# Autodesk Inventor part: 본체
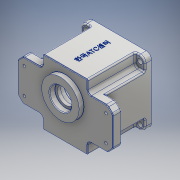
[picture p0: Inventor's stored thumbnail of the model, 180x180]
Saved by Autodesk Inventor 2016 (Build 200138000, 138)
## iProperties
Created: 2017-01
Part Number: 본체
Material: 알루미늄 6061
Document SubType Name: Modeling
Designer: Owner
Density: 2.7 g/cm^3
Appearance: 알루미늄 - 평지
Mass: 908.782 g
Surface Area: 776.692 cm^2
Volume: 336.586 cm^3
Author: Owner
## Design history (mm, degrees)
sketch "스케치1"
  geometry: L1 (70, 30)-(33, 30); L2 (33, 30)-(33, 48); L3 (33, 48)-(-33, 48); L4 (-33, 48)-(-33, 30); L5 (-33, 30)-(-70, 30); L6 (-70, 30)-(-70, -30); L7 (-70, -30)-(-33, -30); L8 (-33, -30)-(-33, -48); L9 (33, -48)-(33, -30); L10 (70, -30)-(70, 30); L11 (70, -30)-(33, -30); L12 (33, -48)-(-33, -48); 1 further point
  constraints: 24 end point, 8 point on line, 5 perpendicular, 3 horizontal, 1 parallel
  dimensions: "d0" = 140 distance between parallel lines of L6 L10; "d2" = 96 distance between parallel lines of L12 L3; "d3" = 70 horizontal distance of L5.end point (0, 0); "d4" = 48 vertical distance of point (0, 0) L3.end; "d5" = 60 distance between parallel lines of L7 L5; "d6" = 30 vertical distance of point (0, 0) L5.end; "d7" = 33 horizontal distance of point (0, 0) L4.end; "d8" = 33 horizontal distance of point (0, 0) L1.end
extrude "돌출1" new body sketch "스케치1" distance "d9" = 13; taper "d10" = 0 deg
sketch "스케치3"
  geometry: L1 (33, -48)-(-33, -48); L2 (-33, -30)-(-33, -48) reference; L3 (-33, -48)-(-33, -30); L4 (-33, -30)-(-47, -30); L5 (-70, -30)-(-33, -30) reference; L6 (-33, 30)-(-70, 30) reference; L7 (-47, 30)-(-33, 30); L8 (-33, 48)-(-33, 30) reference; L9 (-33, 30)-(-33, 48); L10 (33, 48)-(-33, 48) reference; L11 (-33, 48)-(33, 48); L12 (33, 30)-(33, 48) reference; L13 (33, 48)-(33, 30); L14 (33, 30)-(47, 30); L15 (70, 30)-(33, 30) reference; L16 (33, -30)-(70, -30) reference; L17 (47, -30)-(33, -30); L18 (47, -30)-(47, 30); L19 (-47, -30)-(-47, 30); L20 (33, -48)-(33, -30) reference; L21 (33, -48)-(33, -30); 1 further point
  constraints: 24 end point, 6 collinear, 4 point on line, 2 perpendicular, 1 horizontal, 1 vertical
  dimensions: "d12" = 94 distance between parallel lines of L18 L19; "d13" = 47 distance from line of L19 point (0, 0)
extrude "돌출2" join sketch "스케치3" distance "d14" = 57; taper "d15" = 0 deg
sketch "스케치4"
  geometry: L1 (-47, 48)-(47, 48); L2 (47, 48)-(47, -48); L3 (47, -48)-(-47, -48); L4 (-47, -48)-(-47, 48); L5 (-47, 48)-(47, -48); L6 (47, 48)-(-47, -48); L7 (-33, -48)-(33, -48) reference; 2 further points
  constraints: 12 end point, 4 midpoint, 2 parallel, 1 horizontal, 1 perpendicular
  dimensions: "d16" = 94 distance between parallel lines of L4 L2
extrude "돌출3" join sketch "스케치4" distance "d17" = 10; taper "d18" = 0 deg
sketch "스케치5"
  geometry: L1 (0, 0)-(66, 0) reference; L2 (-14, 80)-(80, 80) reference; 3 further points
  constraints: 1 midpoint, 1 vertical alignment, 1 other
  dimensions: "d19" = 40 distance from line of L2 point (33, 40)
feature "엠보싱1" sketch "스케치5" dims "d20" = 0.5, "d21" = 0
sketch "스케치6"
  geometry: L1 (9, 0)-(80, 0); L2 (80, 0)-(80, 43); L3 (80, -48)-(80, 48) reference; L4 (80, 43)-(71, 43); L5 (71, 43)-(71, 40); L6 (71, 40)-(9, 40); L7 (9, 40)-(9, 0); 1 further point
  constraints: 12 end point, 4 perpendicular, 2 horizontal, 1 midpoint, 1 point on line
  dimensions: "d23" = 86 diameter of L4 L1; "d24" = 80 diameter of L6 L1; "d25" = 9 distance of L2.end L4.end; "d26" = 71 distance between parallel lines of L2 L7
revolve "회전1" sketch "스케치6" stored, may be unused: angle "d27" = 90 deg
sketch "스케치7"
  geometry: C1 r 27.5 at (0, 11); 1 further point
  constraints: 1 centre point, 1 vertical alignment
  dimensions: "d28" = 55 diameter of C1; "d29" = 11 distance of point (0, 0) C1.centre
extrude "돌출4" join sketch "스케치7" distance "d30" = 7; taper "d31" = 0 deg
sketch "스케치8"
  geometry: C1 r 21 at (0, -11); 1 further point
  constraints: 1 centre point, 1 vertical alignment
  dimensions: "d32" = 11 distance of point (0, 0) C1.centre; "d33" = 42 diameter of C1
extrude "돌출5" join sketch "스케치8" distance "d34" = 7; taper "d35" = 0 deg
sketch "스케치10" dims "d0" = 140, "d2" = 96, "d3" = 70, "d4" = 48, "d5" = 60, "d6" = 30, "d7" = 33, "d8" = 33
  geometry: L1 (-7, 27)-(1, 27); L2 (1, 27)-(1, 23.5); L3 (1, 23.5)-(6, 23.5); L4 (6, 23.5)-(6, 28.5); L5 (6, 28.5)-(16, 28.5); L6 (-7, 11)-(16, 11); L7 (16, 28.5)-(16, 11); L8 (-7, 27)-(-7, 11); L9 (-7, 38.5)-(-7, -16.5) reference; 1 further point
  constraints: 16 end point, 5 perpendicular, 2 horizontal, 1 point on line
  dimensions: "d36" = 11 distance from line of point (0, 0) L6; "d37" = 23 distance of L6.start L6.end; "d38" = 25 diameter of L3 L6; "d39" = 32 diameter of L1 L6; "d40" = 35 diameter of L5 L6; "d41" = 8 distance of L1.start L1.end; "d42" = 5 distance of L2.end L3.end
revolve "회전2" sketch "스케치10" stored, may be unused: angle "d43" = 90 deg
sketch "스케치11"
  geometry: A1 r 15 centre (0, 31) between (11.584, 21.47) and (-11.584, 21.47); A2 r 21 centre (0, 0) between (12.163, 17.119) and (-12.163, 17.119) reference; A3 r 3 centre (-13.901, 19.565) between (-12.163, 17.119) and (-11.584, 21.47); A4 r 3 centre (13.901, 19.565) between (11.584, 21.47) and (12.163, 17.119); 1 further point
  constraints: 8 point on circle, 4 tangent, 3 centre point, 1 vertical alignment
  dimensions: "d44" = 30 diameter of A1; "d45" = 20 distance of A1.centre point (0, 11); "d46" = 6 diameter of A4; "d47" = 6 diameter of A3
extrude "돌출6" join sketch "스케치11" stored distance "d48" = 7; taper "d49" = 0 deg
sketch "스케치12"
  geometry: C1 r 11 at (0, 20); 1 further point
  constraints: 1 centre point, 1 vertical alignment
  dimensions: "d50" = 20 distance of point (0, 0) C1.centre; "d51" = 22 diameter of C1
extrude "돌출7" cut sketch "스케치12" distance "d52" = 7; taper "d53" = 0 deg
sketch "스케치13"
  geometry: C1 r 9.5 at (0, 0); 1 further point
  constraints: 1 centre point, 1 vertical alignment
  dimensions: "d54" = 19 diameter of C1; "d55" = 20 distance of C1.centre point (0, -20)
extrude "돌출8" cut sketch "스케치13" distance "d56" = 1; taper "d57" = 0 deg
sketch "스케치14"
  geometry: A1 r 4 centre (-36, 0) between (-35.852, -3.997) and (-35.852, 3.997); A2 r 4 centre (36, 0) between (35.852, 3.997) and (35.852, -3.997); A3 r 40 centre (0, 0) between (39.148, -8.214) and (39.148, 8.214) reference; A4 r 3.5 centre (35.722, -7.495) between (39.148, -8.214) and (35.852, -3.997); A5 r 3.5 centre (35.722, 7.495) between (35.852, 3.997) and (39.148, 8.214); A6 r 3.5 centre (-35.722, 7.495) between (-39.148, 8.214) and (-35.852, 3.997); A7 r 3.5 centre (-35.722, -7.495) between (-35.852, -3.997) and (-39.148, -8.214); 1 further point
  constraints: 16 point on circle, 10 tangent, 6 centre point, 2 horizontal alignment
  dimensions: "d58" = 8 diameter of A2; "d59" = 8 diameter of A1; "d62" = 7 diameter of A4; "d63" = 7 diameter of A5; "d64" = 7 diameter of A6; "d65" = 7 diameter of A7
extrude "돌출10" join sketch "스케치14" stored distance "d66" = 1; taper "d67" = 0 deg
chamfer "모따기2" distance "d106" = 8; stored, may be unused: second distance "d107" = 2, angle "d108" = 45 deg
sketch "스케치19"
  geometry: 2 further points
  dimensions: "d84" = 40 horizontal distance of point (0, 0) point (40, 40); "d85" = 40 horizontal distance of point (40, 40) point (0, 0)
hole "구멍2" sketch "스케치19" at (40, 40) diameter "d86" = 7; stored, may be unused: countersink angle "d90" = 90 deg, drill point angle "d92" = 0 deg; dims "d87" = 6, "d88" = 10, "d89" = 4, "d91" = 8
sketch "스케치20"
  geometry: 2 further points
  dimensions: "d93" = 19 vertical distance of point (0, 0) point (60, 19); "d94" = 60 horizontal distance of point (0, 0) point (60, 19)
hole "구멍3" sketch "스케치20" at (60, 19) diameter "d95" = 4; stored, may be unused: countersink angle "d99" = 90 deg, drill point angle "d101" = 0 deg; dims "d96" = 6, "d97" = 10, "d98" = 4, "d100" = 8
fillet "모깎기1" dims "d102" = 8
fillet "모깎기6" dims "d116" = 2
fillet "모깎기7" dims "d117" = 0.3
fillet "모깎기9" dims "d119" = 2
fillet "모깎기10" dims "d120" = 0.3
fillet "모깎기11" dims "d121" = 0.3
fillet "모깎기12" dims "d122" = 5
fillet "모깎기13" dims "d123" = 2
hole "구멍4" diameter "d130" = 3.459; stored, may be unused: countersink angle "d134" = 90 deg, drill point angle "d136" = 118 deg; dims "d128" = 10, "d129" = 10, "d131" = 7, "d132" = 10, "d133" = 4, "d135" = 9
hole "구멍5" diameter "d139" = 3.459; stored, may be unused: countersink angle "d143" = 90 deg, drill point angle "d145" = 118 deg; dims "d137" = 10, "d138" = 10, "d140" = 7, "d141" = 10, "d142" = 4, "d144" = 9
fillet "모깎기15" dims "d146" = 5
fillet "모깎기16" dims "d147" = 2
fillet "모깎기17" dims "d148" = 2
sketch "스케치23"
  geometry: L1 (31, -48)-(-31, -48) reference; L2 (33, -35)-(33, -46) reference; L3 (59.929, -30)-(38, -30) reference; L4 (68.536, -23.464)-(63.464, -28.536) reference; L5 (70, 19.929)-(70, -19.929) reference; L6 (63.464, 28.536)-(68.536, 23.464) reference; L7 (38, 30)-(59.929, 30) reference; L8 (33, 46)-(33, 35) reference; L9 (-31, 48)-(31, 48) reference; L10 (-33, 35)-(-33, 46) reference; L11 (-59.929, 30)-(-38, 30) reference; L12 (-68.536, 23.464)-(-63.464, 28.536) reference; L13 (-70, -19.929)-(-70, 19.929) reference; L14 (-63.464, -28.536)-(-68.536, -23.464) reference; L15 (-38, -30)-(-59.929, -30) reference; L16 (-33, -46)-(-33, -35) reference; L17 (-32, -46)-(-32, -35); L18 (-38, -29)-(-59.929, -29); L19 (-62.757, -27.828)-(-67.828, -22.757); L20 (-69, -19.929)-(-69, 19.929); L21 (-67.828, 22.757)-(-62.757, 27.828); L22 (-59.929, 29)-(-38, 29); L23 (-32, 35)-(-32, 46); L24 (-31, 47)-(31, 47); L25 (32, 46)-(32, 35); L26 (38, 29)-(59.929, 29); L27 (62.757, 27.828)-(67.828, 22.757); L28 (69, 19.929)-(69, -19.929); L29 (67.828, -22.757)-(62.757, -27.828); L30 (59.929, -29)-(38, -29); L31 (32, -35)-(32, -46); L32 (31, -47)-(-31, -47); C1 r 2 at (60, -19) reference; C2 r 2 at (-60, -19) reference; C3 r 2 at (60, 19) reference; C4 r 2 at (-60, 19) reference; C5 r 27.8 at (0, 11) reference; A1 r 2 centre (-31, -46) between (-33, -46) and (-31, -48) reference; A2 r 2 centre (31, -46) between (31, -48) and (33, -46) reference; A3 r 5 centre (38, -35) between (38, -30) and (33, -35) reference; A4 r 5 centre (59.929, -25) between (59.929, -30) and (63.464, -28.536) reference; A5 r 5 centre (65, -19.929) between (68.536, -23.464) and (70, -19.929) reference; A6 r 5 centre (65, 19.929) between (70, 19.929) and (68.536, 23.464) reference; A7 r 5 centre (59.929, 25) between (63.464, 28.536) and (59.929, 30) reference; A8 r 5 centre (38, 35) between (33, 35) and (38, 30) reference; A9 r 2 centre (31, 46) between (33, 46) and (31, 48) reference; A10 r 2 centre (-31, 46) between (-31, 48) and (-33, 46) reference; A11 r 5 centre (-38, 35) between (-38, 30) and (-33, 35) reference; A12 r 5 centre (-59.929, 25) between (-59.929, 30) and (-63.464, 28.536) reference; A13 r 5 centre (-65, 19.929) between (-68.536, 23.464) and (-70, 19.929) reference; A14 r 5 centre (-65, -19.929) between (-70, -19.929) and (-68.536, -23.464) reference; A15 r 5 centre (-59.929, -25) between (-63.464, -28.536) and (-59.929, -30) reference; A16 r 5 centre (-38, -35) between (-33, -35) and (-38, -30) reference; A17 r 1 centre (-31, -46) between (-32, -46) and (-31, -47); A18 r 6 centre (-38, -35) between (-32, -35) and (-38, -29); A19 r 4 centre (-59.929, -25) between (-62.757, -27.828) and (-59.929, -29); A20 r 4 centre (-65, -19.929) between (-69, -19.929) and (-67.828, -22.757); A21 r 4 centre (-65, 19.929) between (-67.828, 22.757) and (-69, 19.929); A22 r 4 centre (-59.929, 25) between (-59.929, 29) and (-62.757, 27.828); A23 r 6 centre (-38, 35) between (-38, 29) and (-32, 35); A24 r 1 centre (-31, 46) between (-31, 47) and (-32, 46); A25 r 1 centre (31, 46) between (32, 46) and (31, 47); A26 r 6 centre (38, 35) between (32, 35) and (38, 29); A27 r 4 centre (59.929, 25) between (62.757, 27.828) and (59.929, 29); A28 r 4 centre (65, 19.929) between (69, 19.929) and (67.828, 22.757); A29 r 4 centre (65, -19.929) between (67.828, -22.757) and (69, -19.929); A30 r 4 centre (59.929, -25) between (59.929, -29) and (62.757, -27.828); A31 r 6 centre (38, -35) between (38, -29) and (32, -35); A32 r 1 centre (31, -46) between (31, -47) and (32, -46); 1 further point
  constraints: 32 end point, 32 point on circle, 16 centre point, 31 other
  dimensions: "d149" = 1 distance between parallel lines of L1 L32
extrude "돌출14" cut sketch "스케치23" distance "d150" = 1; taper "d151" = 0 deg
chamfer "모따기3" distance "d152" = 1; stored, may be unused: second distance "d153" = 2, angle "d154" = 45 deg
chamfer "모따기4" distance "d155" = 1; stored, may be unused: second distance "d156" = 2, angle "d157" = 45 deg
chamfer "모따기5" distance "d158" = 1; stored, may be unused: second distance "d159" = 2, angle "d160" = 45 deg
node "솔리드1"
mirror "대칭3"
mirror "대칭4"
mirror "대칭5"
mirror "대칭6"
node "투영된 루프4"
